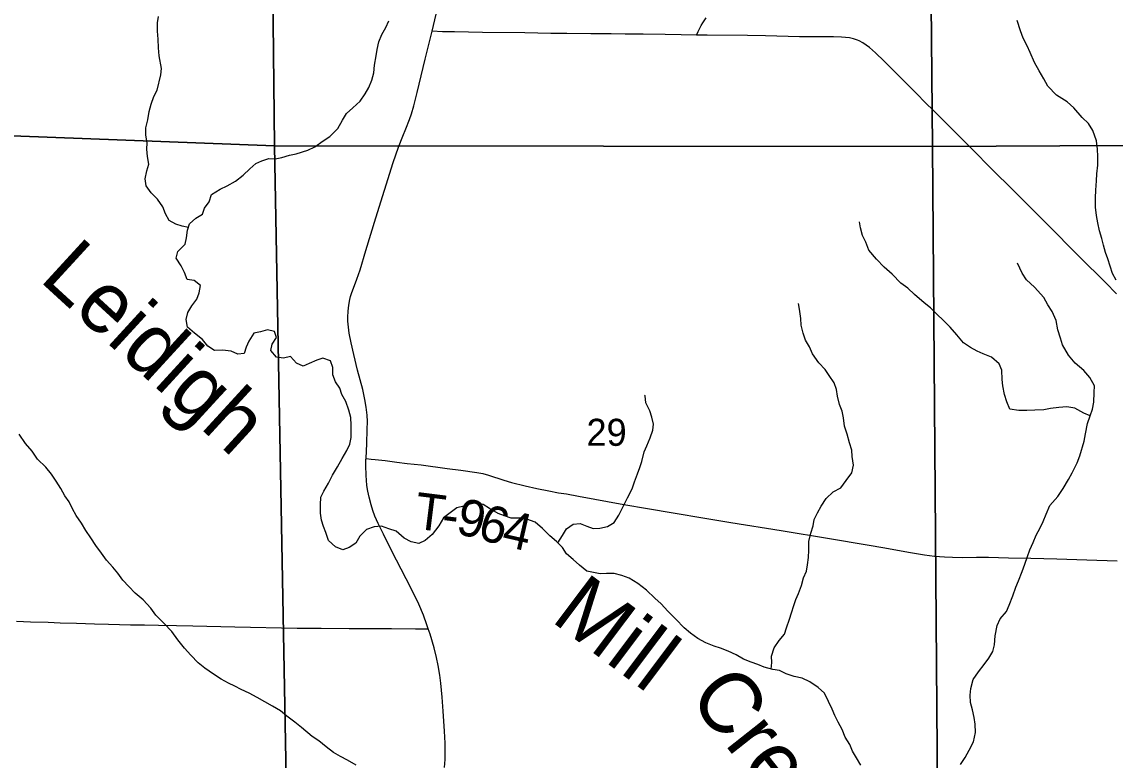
# Model space of a CAD drawing. Extents: x 1874609 to 2204689, y 815661 to 1281160.
# Drawn here: x 2016181 to 2025118, y 1062426 to 1068461 of the extents above; entities that cross this region are included whole.
import ezdxf

# ---------------------------------------------------------------- set-up
doc = ezdxf.new("R2010")
doc.units = 0
for name, color, linetype in [('GM_X_Minor_River', 7, 'Continuous'), ('GM_X_Minor_River_Text', 7, 'Continuous'), ('GM_X_Section', 7, 'Continuous'), ('GM_X_Section_Text', 7, 'Continuous'), ('GM_X_State_Route', 7, 'Continuous'), ('GM_X_Township_Road', 7, 'Continuous'), ('GM_X_Township_Road_Text', 7, 'Continuous')]:
    doc.layers.add(name, color=color, linetype=linetype)

msp = doc.modelspace()

# ---------------------------------------------------------------- linework, layer by layer
at = {"layer": 'GM_X_Minor_River'}
for points in [[(2017542.7, 1066779), (2017492.3, 1066791.8), (2017440.3, 1066806.2), (2017386.4, 1066836.6), (2017356.6, 1066891), (2017332.9, 1066949.3), (2017291.2, 1067011.8), (2017237.3, 1067064.3), (2017197.6, 1067120.8), (2017189.9, 1067177), (2017202.2, 1067243.1), (2017220.6, 1067299.2), (2017208.9, 1067361.5), (2017203.2, 1067421.7), (2017205.5, 1067471.8), (2017193.8, 1067536.1), (2017196.1, 1067594.3), (2017212.5, 1067660.4), (2017222.8, 1067728.6), (2017237.2, 1067788.7), (2017261.6, 1067850.7), (2017287.9, 1067902.7), (2017316.6, 1068028.9), (2017322.9, 1068079.1), (2017303.4, 1068183.5), (2017299.7, 1068247.8), (2017296.1, 1068320), (2017290.4, 1068384.2), (2017290.8, 1068454.5), (2017297.1, 1068504.6)], [(2017642, 1066307.2), (2017590.1, 1066345.7), (2017532.1, 1066354.1), (2017510.4, 1066412.4), (2017482.6, 1066466.8), (2017442.9, 1066529.2), (2017457.2, 1066585.3), (2017515.6, 1066645.2), (2017527.9, 1066695.2), (2017536.2, 1066757.4), (2017552.6, 1066811.5), (2017602.9, 1066857.3), (2017657.1, 1066889), (2017673.4, 1066939.1), (2017711.8, 1066991), (2017732.1, 1067049.1), (2017802.5, 1067092.8), (2017858.7, 1067120.5), (2017929.1, 1067160.2), (2017991.4, 1067207.9), (2018043.8, 1067259.8), (2018094.1, 1067303.6), (2018144.3, 1067325.3), (2018200.5, 1067343), (2018252.6, 1067342.7), (2018306.7, 1067352.3), (2018369, 1067372), (2018423.1, 1067381.7), (2018519.4, 1067411.2), (2018575.7, 1067440.9), (2018644.1, 1067488.6), (2018700.3, 1067524.4), (2018764.8, 1067588.2), (2018801.2, 1067658.2), (2018835.6, 1067712.1), (2018885.9, 1067757.9), (2018946.3, 1067811.7), (2018986.7, 1067871.7), (2019019, 1067925.6), (2019043.4, 1067983.6), (2019059.7, 1068045.8), (2019064.1, 1068105.9), (2019076.5, 1068184.1), (2019086.8, 1068234.2), (2019099.1, 1068298.3), (2019123.5, 1068358.3), (2019155.9, 1068416.3), (2019182.2, 1068468.3)], [(2025126.1, 1066350.9), (2025097.5, 1066402.9), (2025077, 1066462.9), (2025058.4, 1066525), (2025040, 1066575.1), (2025023.4, 1066635.1), (2025008.9, 1066691.2), (2024990.3, 1066753.3), (2024975.8, 1066819.4), (2024965.3, 1066877.5), (2024958.7, 1066945.7), (2024958, 1067024), (2024959.5, 1067084.2), (2024964.9, 1067160.5), (2024968.5, 1067218.7), (2024975.9, 1067289), (2024977.3, 1067359.3), (2024974.8, 1067421.5), (2024966.2, 1067489.6), (2024935.5, 1067573.7), (2024900.9, 1067629.7), (2024848.3, 1067679.4), (2024779.5, 1067757.2), (2024726.9, 1067807), (2024638.2, 1067862.5), (2024567.4, 1067936.2), (2024534.8, 1067994.2), (2024498.2, 1068060.1), (2024459.5, 1068128.1), (2024422.7, 1068210.1), (2024398.2, 1068264.1), (2024367.6, 1068328.1), (2024345, 1068388.1), (2024316.2, 1068472.2)], [(2024914.6, 1065241.5), (2024862.2, 1065263.2), (2024787.7, 1065302.8), (2024723.4, 1065314.3), (2024657.2, 1065307.8), (2024591.1, 1065299.3), (2024535, 1065290.8), (2024462.8, 1065286.3), (2024396.7, 1065283.8), (2024330.5, 1065285.3), (2024258.2, 1065294.8), (2024233.6, 1065354.8), (2024213, 1065414.9), (2024200.4, 1065487.1), (2024194, 1065537.2), (2024193.3, 1065613.4), (2024170.8, 1065665.4), (2024108.2, 1065719.2), (2024039.8, 1065746.8), (2023989.5, 1065768.5), (2023935, 1065800.2), (2023878.6, 1065837.9), (2023823.9, 1065903.7), (2023771.2, 1065965.5), (2023716.6, 1066021.3), (2023662, 1066073.1), (2023609.4, 1066122.9), (2023556.9, 1066164.6), (2023478.1, 1066232.3), (2023423.5, 1066284.1), (2023367, 1066325.8), (2023296.2, 1066397.5), (2023229.5, 1066455.2), (2023166.8, 1066521), (2023106, 1066594.8), (2023079.4, 1066660.8), (2023052.9, 1066714.8), (2023036.3, 1066776.9), (2023027.9, 1066827)], [(2023854.9, 1062389.6), (2023892.5, 1062448.1), (2023926.1, 1062508.5), (2023959.6, 1062577), (2023977.1, 1062653.4), (2023974.5, 1062719.6), (2023966, 1062775.8), (2023953.5, 1062837.9), (2023936.9, 1062898), (2023934.4, 1062958.2), (2023938, 1063012.4), (2023957.5, 1063084.8), (2024001, 1063149.3), (2024046.7, 1063207.9), (2024086.4, 1063260.4), (2024118, 1063314.8), (2024131.6, 1063369.1), (2024137, 1063441.4), (2024154.4, 1063527.8), (2024178, 1063582.2), (2024231.7, 1063640.8), (2024251.3, 1063693.1), (2024282.8, 1063769.6), (2024306.3, 1063840.1), (2024327.9, 1063892.4), (2024359.4, 1063966.9), (2024380.9, 1064027.3), (2024402.5, 1064089.6), (2024422.1, 1064144), (2024447.7, 1064206.4), (2024473.3, 1064264.8), (2024506.9, 1064325.3), (2024530.5, 1064377.6), (2024554.1, 1064436), (2024585.6, 1064506.5), (2024651.2, 1064581.2), (2024692.8, 1064645.8), (2024736.3, 1064720.3), (2024767.9, 1064774.8), (2024807.4, 1064857.3), (2024829, 1064913.7), (2024864.1, 1065034.4), (2024875.7, 1065092.7), (2024893, 1065177.1), (2024914.6, 1065241.5), (2024932.2, 1065295.8), (2024943.7, 1065352.1), (2024947.1, 1065432.4), (2024948.6, 1065484.6), (2024912, 1065554.6), (2024861.4, 1065610.4), (2024790.6, 1065672.1), (2024735.9, 1065737.9), (2024689.1, 1065819.8), (2024670.6, 1065875.9), (2024650, 1065944), (2024635.3, 1066020.1), (2024604.6, 1066094.2), (2024568.1, 1066148.1), (2024535.5, 1066208), (2024458.6, 1066291.8), (2024393.9, 1066351.5), (2024357.3, 1066407.4), (2024320.5, 1066487.4)], [(2021215.4, 1063870.2), (2021145.5, 1063914.8), (2021085.5, 1063935.2), (2021023.5, 1063951.7), (2020961.4, 1063952.1), (2020909.3, 1063948.4), (2020853.2, 1063960.8), (2020799.2, 1063971.2), (2020739.3, 1064019.7), (2020687.5, 1064066.2), (2020633.6, 1064112.7), (2020601.9, 1064163.1), (2020552, 1064213.6), (2020498.2, 1064260.1), (2020436.4, 1064318.7), (2020376.6, 1064371.2), (2020310.6, 1064395.7), (2020256.5, 1064404.1), (2020180.4, 1064404.6), (2020126.4, 1064423), (2020074.4, 1064443.4), (2020004.5, 1064482), (2019952.6, 1064516.4), (2019898.6, 1064530.8), (2019844.4, 1064519.2), (2019794.2, 1064503.4), (2019736.1, 1064489.8), (2019627.4, 1064406.2), (2019591, 1064342.2), (2019536.6, 1064270.3), (2019478.2, 1064222.5), (2019426, 1064196.8), (2019364, 1064211.2), (2019306, 1064239.7), (2019242.2, 1064298.3), (2019180.2, 1064316.8), (2019122.2, 1064339.2), (2019062.1, 1064333.6), (2018999.8, 1064311.9), (2018943.4, 1064256.1), (2018911.1, 1064200.1), (2018856.8, 1064164.3), (2018804.6, 1064144.6), (2018744.7, 1064171.1), (2018686.8, 1064221.6), (2018667.1, 1064286), (2018647.4, 1064336.3), (2018631.6, 1064386.5), (2018623.9, 1064444.8), (2018622.3, 1064513), (2018626.6, 1064575.2), (2018648.9, 1064625.2), (2018689.3, 1064691.2), (2018721.7, 1064755.2), (2018762.1, 1064823.1), (2018800.6, 1064893.1), (2018837, 1064957.1), (2018861.3, 1065009.1), (2018873.6, 1065063.2), (2018874.1, 1065163.5), (2018870.5, 1065225.8), (2018854.7, 1065286.1), (2018829.1, 1065358.5), (2018797.3, 1065414.9), (2018781.6, 1065467.1), (2018745.8, 1065519.5), (2018724.1, 1065575.9), (2018722.4, 1065636.1), (2018704.6, 1065690.4), (2018642.6, 1065712.8), (2018592.5, 1065695.1), (2018530.2, 1065669.4), (2018480, 1065645.7), (2018426, 1065670.1), (2018376.2, 1065724.6), (2018320.1, 1065710.9), (2018262, 1065719.3), (2018216.2, 1065775.8), (2018226.5, 1065825.9), (2018262.9, 1065879.8), (2018247.1, 1065930.1), (2018189.1, 1065942.5), (2018130.9, 1065926.8), (2018076.7, 1065915.2), (2018036.3, 1065851.2), (2018014, 1065801.2), (2017999.7, 1065751.1), (2017945.6, 1065745.4), (2017893.6, 1065769.9), (2017821.5, 1065778.3), (2017757.4, 1065774.8), (2017701.5, 1065811.2), (2017657.7, 1065863.7), (2017591.9, 1065916.3), (2017536, 1065964.8), (2017524.3, 1066027.1), (2017538.7, 1066085.2), (2017571, 1066141.2), (2017611.4, 1066195.1), (2017631.7, 1066245.1), (2017642, 1066307.2)], [(2022307.9, 1063170.2), (2022311.9, 1063225), (2022308.2, 1063275.2), (2022330.5, 1063343.3), (2022372.9, 1063403.2), (2022415.3, 1063457.1), (2022431.6, 1063507.2), (2022456, 1063579.2), (2022472.3, 1063631.3), (2022490.7, 1063689.4), (2022509, 1063739.4), (2022531.3, 1063789.5), (2022553.6, 1063853.5), (2022572, 1063917.6), (2022594.3, 1063969.7), (2022604.6, 1064021.8), (2022610.9, 1064081.9), (2022613.3, 1064142.1), (2022615.6, 1064212.3), (2022632, 1064282.4), (2022650.4, 1064340.5), (2022658.7, 1064394.6), (2022685, 1064448.7), (2022715.4, 1064502.6), (2022755.8, 1064564.6), (2022812.1, 1064620.4), (2022876.4, 1064652.1), (2022920.8, 1064712), (2022967.2, 1064773.9), (2022979.6, 1064838.1), (2022967.9, 1064908.4), (2022966.2, 1064960.6), (2022946.5, 1065018.9), (2022928.8, 1065091.2), (2022907.1, 1065155.6), (2022897.5, 1065223.9), (2022885.8, 1065278.1), (2022864, 1065334.4), (2022848.3, 1065402.8), (2022840.6, 1065457), (2022820.9, 1065509.3), (2022781.1, 1065569.7), (2022749.3, 1065620.1), (2022697.5, 1065674.6), (2022643.8, 1065747.2), (2022620.1, 1065803.6), (2022588.3, 1065859.9), (2022568.6, 1065916.2), (2022550.9, 1065980.6), (2022549.2, 1066036.8), (2022541.5, 1066093), (2022531.7, 1066145.2), (2022529.8, 1066159.3)], [(2020562, 1064203.5), (2020600.4, 1064263.4), (2020634.7, 1064317.4), (2020689, 1064355.2), (2020745.2, 1064360.8), (2020799.1, 1064338.4), (2020851.1, 1064320), (2020907.2, 1064321.7), (2020969.4, 1064335.3), (2021023.7, 1064369.1), (2021062.1, 1064429), (2021092.4, 1064489), (2021130.9, 1064569.1), (2021169.4, 1064645.1), (2021189.7, 1064701.1), (2021214.1, 1064767.2), (2021232.4, 1064817.2), (2021248.7, 1064867.3), (2021269.2, 1064945.4), (2021291.5, 1064995.4), (2021317.9, 1065061.5), (2021340.2, 1065123.5), (2021344.5, 1065173.7), (2021330.8, 1065229.9), (2021315, 1065282.2), (2021283.3, 1065346.6), (2021275.6, 1065402.9), (2021271.6, 1065410.9)], [(2017456.4, 1063408.9), (2017406.6, 1063477.4), (2017340.9, 1063546.1), (2017277.1, 1063610.7), (2017235.4, 1063669.2), (2017173.6, 1063737.8), (2017107.8, 1063790.4), (2017056, 1063844.9), (2017006.2, 1063897.4), (2016966.4, 1063953.8), (2016924.6, 1064004.3), (2016872.8, 1064060.8), (2016833, 1064119.3), (2016787.3, 1064181.8), (2016745.5, 1064242.2), (2016703.8, 1064304.7), (2016670, 1064363.1), (2016624.3, 1064425.6), (2016594.5, 1064480), (2016566.8, 1064536.4), (2016533, 1064586.7), (2016499.2, 1064647.2), (2016461.5, 1064707.6), (2016423.7, 1064764), (2016378, 1064820.5), (2016310.2, 1064887.2), (2016264.5, 1064951.7), (2016210.7, 1065014.2), (2016159, 1065090.8)], [(2023040.7, 1062385.5), (2023003, 1062445.9), (2022971.2, 1062498.3), (2022949.5, 1062554.6), (2022911.7, 1062615.1), (2022888, 1062677.5), (2022854.3, 1062737.9), (2022826.5, 1062792.2), (2022804.7, 1062842.6), (2022775, 1062904.9), (2022743.3, 1062973.4), (2022689.5, 1063019.9), (2022621.6, 1063066.5), (2022559.6, 1063095), (2022493.6, 1063109.4), (2022429.6, 1063131.9), (2022375.6, 1063158.4), (2022321.6, 1063166.7), (2022249.6, 1063185.2), (2022197.6, 1063207.7), (2022143.6, 1063228.1), (2022079.6, 1063252.6), (2022021.7, 1063287.1), (2021953.8, 1063317.6), (2021893.8, 1063342.1), (2021839.8, 1063356.5), (2021771.8, 1063385), (2021707.9, 1063419.5), (2021646, 1063464.1), (2021594.1, 1063506.5), (2021526.4, 1063577.2), (2021460.6, 1063643.8), (2021406.8, 1063704.4), (2021355, 1063748.9), (2021287.2, 1063815.5), (2021215.4, 1063870.2)], [(2018913.5, 1062384), (2018843.6, 1062426.6), (2018785.6, 1062455.1), (2018729.7, 1062489.6), (2018669.9, 1062536.1), (2018608, 1062582.7), (2018554.1, 1062619.1), (2018466.3, 1062691.9), (2018412.5, 1062736.4), (2018348.6, 1062785), (2018296.8, 1062829.5), (2018230.9, 1062868.1), (2018168.9, 1062902.6), (2018105, 1062939.1), (2018039.1, 1062973.6), (2017975.1, 1063004.2), (2017923.2, 1063030.6), (2017871.2, 1063055), (2017811.3, 1063087.5), (2017747.4, 1063130.1), (2017677.5, 1063178.7), (2017623.7, 1063221.2), (2017563.9, 1063283.8), (2017510.1, 1063342.3), (2017456.4, 1063408.9)]]:
    msp.add_lwpolyline(points, dxfattribs=at)
at = {"layer": 'GM_X_Section'}
for points in [[(2018190, 1072759.5), (2018247.2, 1067446.7), (2012811.7, 1067655.4), (2012766.6, 1072920.2)], [(2018190, 1072759.5), (2023577.1, 1072706.8), (2023626.2, 1067442), (2018247.2, 1067446.7)], [(2028774, 1072757.7), (2028833.1, 1067470.8), (2023626.2, 1067442), (2023577.1, 1072706.8)], [(2012811.7, 1067655.4), (2018247.2, 1067446.7), (2018344.4, 1062132), (2012875, 1062308.6)], [(2023626.2, 1067442), (2023667.3, 1062153.1), (2018344.4, 1062132), (2018247.2, 1067446.7)], [(2028833.1, 1067470.8), (2028904.1, 1062206), (2023667.3, 1062153.1), (2023626.2, 1067442)]]:
    msp.add_lwpolyline(points, close=True, dxfattribs=at)
at = {"layer": 'GM_X_State_Route'}
for points in [[(2019534.9, 1068386.1), (2019600.5, 1068666.4)], [(2019635.8, 1062366.7), (2019641, 1062432.4), (2019642.9, 1062498.2), (2019641.3, 1062563.9), (2019635.5, 1062662), (2019625.6, 1062825.4), (2019616.9, 1062940), (2019605.6, 1063054.4), (2019597.1, 1063119.5), (2019583.8, 1063200.6), (2019570.5, 1063265), (2019550.9, 1063344.8), (2019518.7, 1063455.2), (2019504.1, 1063499.1), (2019492.8, 1063533.2), (2019463.6, 1063610), (2019425.5, 1063701), (2019391, 1063775.5), (2019324, 1063907.2), (2019204.1, 1064140.5), (2019137.4, 1064272.2), (2019094.2, 1064360.4), (2019068, 1064420.2), (2019051.1, 1064466), (2019036.6, 1064512.8), (2019020.3, 1064576.1), (2019010.4, 1064623.9), (2019002.3, 1064671.9), (2018998.4, 1064713.6), (2018996.2, 1064753.7), (2018994.1, 1064834.9), (2018994.3, 1064883.9), (2018994.6, 1064890.7), (2019000.7, 1065014.8), (2019005.3, 1065129.6), (2019005.9, 1065195.4), (2019003.5, 1065244.8), (2018996.6, 1065310.3), (2018985.7, 1065375.3), (2018967.7, 1065455.5), (2018926.2, 1065614.1), (2018894.3, 1065741.2), (2018872.9, 1065837), (2018858.1, 1065917.4), (2018851.5, 1065965.8), (2018847.1, 1066014.4), (2018847, 1066046.8), (2018849.5, 1066095.5), (2018855.2, 1066144), (2018861.7, 1066190.6), (2018866.9, 1066215.4), (2018876, 1066241.4), (2018920.9, 1066357.6), (2018946.9, 1066435.4), (2018994.3, 1066592.4), (2019074.6, 1066859.2), (2019216.2, 1067312.8), (2019259.2, 1067435.8), (2019294.7, 1067527.4), (2019320, 1067587.9), (2019350.6, 1067664.1), (2019366.8, 1067710.7), (2019385.5, 1067773.7), (2019414, 1067885.1), (2019478.6, 1068156.2), (2019534.9, 1068386.1)], [(2025130.2, 1066237.6), (2025039.1, 1066331.2), (2024969.8, 1066400.9), (2024899.1, 1066469.4), (2024840.8, 1066527), (2024748.6, 1066620.2), (2024633.5, 1066737.1), (2024459, 1066910.4), (2024285.1, 1067084.3), (2024111.1, 1067258.2), (2023948.9, 1067420.4), (2023775.9, 1067595.3), (2023635.3, 1067732.7), (2023565.8, 1067802), (2023496.7, 1067872.1), (2023324, 1068047.5), (2023230.4, 1068139.6), (2023158.9, 1068207.2), (2023109.3, 1068250.7), (2023083.2, 1068271), (2023055.7, 1068289.6), (2023026.6, 1068305.7), (2023011.3, 1068312.3), (2022979.8, 1068323), (2022947.4, 1068330.3), (2022914.5, 1068334.6), (2022881.5, 1068336.8), (2022815.7, 1068338.2), (2022668.3, 1068337.7), (2022603.4, 1068337.7), (2022538.4, 1068338.4), (2022260.2, 1068347.2), (2022112.6, 1068349.8), (2021784.8, 1068352), (2021697, 1068353.2), (2021571.9, 1068354.9), (2021440.8, 1068357), (2021260.3, 1068359.3), (2021112.7, 1068361.8), (2020997.8, 1068362.8), (2020833.8, 1068364.2), (2020636.9, 1068366.8), (2020505.6, 1068367), (2020292.4, 1068370.3), (2019948.1, 1068375.5), (2019718.7, 1068379.5), (2019620.5, 1068380.3), (2019534.9, 1068386.1)]]:
    msp.add_lwpolyline(points, dxfattribs=at)
at = {"layer": 'GM_X_Township_Road'}
for points in [[(2021697, 1068353.2), (2021710.3, 1068381.2), (2021724.3, 1068410.9), (2021734.5, 1068431.4), (2021748.5, 1068453.7), (2021776.4, 1068494.3)], [(2018994.6, 1064890.7), (2019037.9, 1064886.9), (2019070.6, 1064884.1), (2019152, 1064874.3), (2019247.5, 1064862.6), (2019331.2, 1064852.4), (2019445.3, 1064838.9), (2019656.8, 1064810.4), (2019770.7, 1064795.6), (2019900.9, 1064778.2), (2019949.2, 1064768.6), (2019996.8, 1064755.9), (2020121.6, 1064714.9), (2020184.6, 1064696.4), (2020296.1, 1064668.4), (2020392, 1064645.9), (2020488.4, 1064626.5), (2020569.3, 1064612.5), (2020634.1, 1064602.3), (2020730.9, 1064583.9), (2021102.2, 1064515.1), (2021295.9, 1064482.3), (2021506.6, 1064447.5), (2021765.6, 1064403.6), (2021976.1, 1064368.8), (2022387.8, 1064304), (2022783.3, 1064238.2), (2022880.4, 1064222.1), (2022993.7, 1064202.8), (2023107, 1064183.9), (2023220.3, 1064164.9), (2023446.2, 1064124.1), (2023560, 1064104.6), (2023640.8, 1064094.2), (2023724.2, 1064087.7), (2023789.3, 1064085.1), (2023870, 1064083.8), (2023985, 1064085.6), (2024083.5, 1064085.6), (2024247.7, 1064081), (2024428.3, 1064077.1), (2024641.6, 1064072.6), (2024887.8, 1064064.1), (2025134, 1064054.4)], [(2016138.4, 1063561.7), (2016253, 1063557.7), (2016395.9, 1063553.5), (2016495.7, 1063549.7), (2016628.7, 1063547.1), (2016775.6, 1063540.7), (2016889.9, 1063536.7), (2017069.8, 1063533.1), (2017184.2, 1063531.3), (2017298.9, 1063530.4), (2017446.7, 1063527.8), (2017577.9, 1063524), (2017922.5, 1063514.6), (2018431.2, 1063506), (2018628.1, 1063504.2), (2018858, 1063503.6), (2019202.7, 1063501.3), (2019399.6, 1063500.6), (2019468.9, 1063499.6), (2019504.1, 1063499.1)]]:
    msp.add_lwpolyline(points, dxfattribs=at)

# ---------------------------------------------------------------- texts
at = {"layer": 'GM_X_Minor_River_Text'}
for s, height, rotation, p in [('Leidigh', 500.16, 317.47553, (2016314.9, 1066351.8)), ('Mill', 500.17, 323.06729, (2020496, 1063569.9)), ('Creek', 500.17, 308.25495, (2021620.9, 1062939.2))]:
    msp.add_text(s, height=height, rotation=rotation, dxfattribs=at).set_placement(p)
at = {"layer": 'GM_X_Section_Text'}
msp.add_text('29', height=221, rotation=0.00001, dxfattribs=at).set_placement((2020796.9, 1064995.6))
at = {"layer": 'GM_X_Township_Road_Text'}
for s, rotation, p in [('T', 352.88934, (2019380.9, 1064320)), ('9', 348.36757, (2019719.6, 1064277.7)), ('6', 342.98872, (2019893.4, 1064242.3)), ('-', 352.76074, (2019603.4, 1064292.2)), ('4', 347.16992, (2020093.2, 1064182.1))]:
    msp.add_text(s, height=300, rotation=rotation, dxfattribs=at).set_placement(p)

doc.saveas('drawing.dxf')
